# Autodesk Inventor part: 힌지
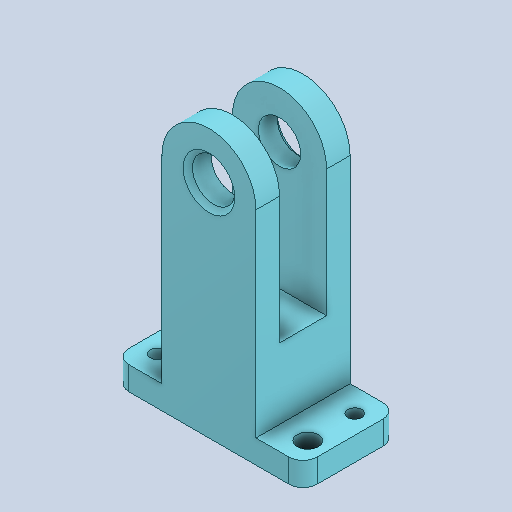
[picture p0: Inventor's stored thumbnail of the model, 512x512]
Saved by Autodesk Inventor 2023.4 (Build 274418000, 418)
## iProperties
Created: 2024-04
Part Number: 힌지
Material: 알루미늄 6061
Document SubType Name: Modeling
Designer: EDU
Density: 2.71 g/cm^3
Appearance: 기본값
Author: jhkim
Sending System: Autodesk Inventor 2025
Preprocessor: ST-DEVELOPER v20
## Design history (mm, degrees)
node "힌지1"
node "솔리드2"
node "솔리드1"
